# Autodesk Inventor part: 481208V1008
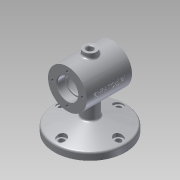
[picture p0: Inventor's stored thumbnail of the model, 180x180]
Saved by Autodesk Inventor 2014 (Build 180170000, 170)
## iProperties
Created: 2018-12
Part Number: 481208V1008
Material: 알루미늄 6061
Document SubType Name: Modeling
Designer: 601-05
Density: 2.71 g/cm^3
Appearance: 알루미늄 - 평지
Author: 601-05
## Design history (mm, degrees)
sketch "스케치1"
  geometry: C1 r 55 at (0, 0); 1 further point
  constraints: 1 centre point, 1 coincident
  dimensions: "d0" = 110 diameter of C1
extrude "돌출1" new body sketch "스케치1" distance "d1" = 11; taper "d2" = 0 deg
sketch "스케치2"
  geometry: L1 (0, 0)-(0, 75); L2 (-35, 75)-(35, 75); L3 (-35, 75)-(-35, 105); L4 (-35, 105)-(35, 105); L5 (35, 105)-(35, 75)
  constraints: 10 end point, 3 perpendicular, 1 midpoint, 1 parallel, 1 vertical
  dimensions: "d3" = 75 distance of L1.end L1.start; "d4" = 70 distance of L2.start L2.end; "d5" = 60 diameter of L4 L2
revolve "회전1" sketch "스케치2" stored, may be unused: angle "d6" = 90 deg
sketch "스케치3"
  geometry: L1 (-55, 0)-(-55, 11) reference; L2 (-55, 11)-(55, 11) reference; L3 (55, 11)-(55, 0) reference; L4 (55, 0)-(-55, 0) reference; L5 (-35, 45)-(-35, 105) reference; L6 (-35, 105)-(35, 105) reference; L7 (35, 105)-(35, 45) reference; L8 (35, 45)-(-35, 45) reference; L9 (0, 0)-(0, 75); L10 (-35, 75)-(-35, 91); L11 (-23, 90.7)-(-23, 89); L12 (-23, 89)-(-20, 89); L13 (-20, 89)-(-20, 97); L14 (-17, 100)-(17, 100); L15 (20, 97)-(20, 89); L16 (20, 89)-(23, 89); L17 (23, 89)-(23, 90.7); L18 (23.3, 91)-(35, 91); L19 (35, 91)-(35, 75); L20 (-23.3, 91)-(-35, 91); L21 (-35, 75)-(35, 75); A1 r 3 centre (-17, 97) between (-17, 100) and (-20, 97); A2 r 3 centre (17, 97) between (20, 97) and (17, 100); A3 r 0.3 centre (-23.3, 90.7) between (-23, 90.7) and (-23.3, 91); A4 r 0.3 centre (23.3, 90.7) between (23.3, 91) and (23, 90.7); 4 further points
  constraints: 26 end point, 10 point on line, 8 point on circle, 8 tangent, 6 parallel, 4 centre point, 3 perpendicular, 2 horizontal, 2 midpoint, 1 collinear, 1 equal radius
  dimensions: "d7" = 32 diameter of L20 L21; "d8" = 28 diameter of L12 L21; "d9" = 50 diameter of L14 L21; "d10" = 32 diameter of L18 L21; "d11" = 28 diameter of L16 L21; "d12" = 12 distance from line of point (-23, 91) L10; "d13" = 40 distance between parallel lines of L15 L13; "d14" = 12 distance of L18.end point (23, 91); "d15" = 3 distance between parallel lines of L13 L11; "d17" = 3 radius of A1; "d73" = 0.3 radius of A3; "d74" = 0.3 radius of A4
revolve "회전2" sketch "스케치3" stored, may be unused: angle "d16" = 90 deg
sketch "스케치4" dims "d19" = 46
  geometry: L1 (0, 0)-(0, 23); C1 r 30 at (0, 0) reference; 2 further points
  constraints: 2 coincident, 2 end point, 1 vertical, 1 vertical alignment, 2 other
hole "구멍1" sketch "스케치4" at (0, 23) diameter "d20" = 4.134; stored, may be unused: countersink angle "d24" = 90 deg, drill point angle "d26" = 118 deg; dims "d21" = 8, "d22" = 4, "d23" = 2, "d25" = 10
node "작업 평면1"
sketch "스케치5"
  geometry: L1 (0, -18.566)-(0, 13.615); L2 (35, 30)-(35, -30) reference; C1 r 10 at (0, 0); 1 further point
  constraints: 2 end point, 1 centre point, 1 coincident, 1 vertical
  dimensions: "d31" = 35 distance between parallel lines of L1 L2; "d32" = 20 diameter of C1
extrude "돌출2" join sketch "스케치5" stored distance "d33" = 10; taper "d34" = 0 deg
sketch "스케치6"
  geometry: C1 r 10 at (0, 0) reference; C2 r 5 at (0, 0)
  constraints: 1 centre point, 1 coincident
  dimensions: "d35" = 10 diameter of C2
extrude "돌출3" cut sketch "스케치6" distance "d36" = 28; taper "d37" = 0 deg
sketch "스케치7"
  geometry: L1 (55, 11)-(0, 25.737); L2 (-55, 0)-(-55, 11) reference; L3 (-55, 11)-(55, 11) reference; L4 (55, 11)-(55, 0) reference; L5 (55, 0)-(-55, 0) reference; L6 (-23.758, 98)-(-25, 100.067) reference; L7 (-25, 100.067)-(-35, 100.067) reference; L8 (-35, 100.067)-(-35, 105) reference; L9 (-35, 105)-(-10, 105) reference; L10 (-10, 105)-(-10, 112) reference; L11 (-10, 112)-(-5, 112) reference; L12 (-5, 112)-(-5, 100) reference; L13 (-5, 100)-(-17, 100) reference; L14 (-20, 97)-(-20, 89) reference; L15 (-20, 89)-(-23, 89) reference; L16 (-23, 89)-(-23, 90.7) reference; L17 (-23.3, 91)-(-35, 91) reference; L18 (-35, 91)-(-35, 95.933) reference; L19 (-35, 95.933)-(-25, 95.933) reference; L20 (-25, 95.933)-(-23.758, 98) reference; L21 (35, 91)-(23.3, 91) reference; L22 (23, 90.7)-(23, 89) reference; L23 (23, 89)-(20, 89) reference; L24 (20, 89)-(20, 97) reference; L25 (17, 100)-(5, 100) reference; L26 (5, 100)-(5, 112) reference; L27 (5, 112)-(10, 112) reference; L28 (10, 112)-(10, 105) reference; L29 (10, 105)-(35, 105) reference; L30 (35, 105)-(35, 100.067) reference; L31 (35, 100.067)-(25, 100.067) reference; L32 (25, 100.067)-(23.758, 98) reference; L33 (23.758, 98)-(25, 95.933) reference; L34 (25, 95.933)-(35, 95.933) reference; L35 (35, 95.933)-(35, 91) reference; L36 (23.3, 59)-(35, 59) reference; L37 (35, 59)-(35, 54.067) reference; L38 (35, 54.067)-(25, 54.067) reference; L39 (25, 54.067)-(23.758, 52) reference; L40 (23.758, 52)-(25, 49.933) reference; L41 (25, 49.933)-(35, 49.933) reference; L42 (35, 49.933)-(35, 45) reference; L43 (35, 45)-(-35, 45) reference; L44 (-35, 45)-(-35, 49.933) reference; L45 (-35, 49.933)-(-25, 49.933) reference; L46 (-25, 49.933)-(-23.758, 52) reference; L47 (-23.758, 52)-(-25, 54.067) reference; L48 (-25, 54.067)-(-35, 54.067) reference; L49 (-35, 54.067)-(-35, 59) reference; L50 (-35, 59)-(-23.3, 59) reference; L51 (-23, 59.3)-(-23, 61) reference; L52 (-23, 61)-(-20, 61) reference; L53 (-20, 61)-(-20, 53) reference; L54 (-17, 50)-(17, 50) reference; L55 (20, 53)-(20, 61) reference; L56 (20, 61)-(23, 61) reference; L57 (23, 61)-(23, 59.3) reference; L58 (20, 10)-(23, 10); L59 (55, 11)-(0, 11); L60 (0, 25.737)-(0, 11); A1 r 3 centre (-17, 97) between (-17, 100) and (-20, 97) reference; A2 r 0.3 centre (-23.3, 90.7) between (-23, 90.7) and (-23.3, 91) reference; A3 r 3 centre (17, 97) between (20, 97) and (17, 100) reference; A4 r 0.3 centre (-23.3, 59.3) between (-23.3, 59) and (-23, 59.3) reference; A5 r 3 centre (-17, 53) between (-20, 53) and (-17, 50) reference; A6 r 3 centre (17, 53) between (17, 50) and (20, 53) reference; A7 r 0.3 centre (23.3, 90.7) between (23.3, 91) and (23, 90.7) reference; A8 r 0.3 centre (23.3, 59.3) between (23, 59.3) and (23.3, 59) reference; 1 further point
  constraints: 8 end point, 5 point on line, 1 midpoint, 1 parallel, 1 perpendicular
  dimensions: "d38" = 75 deg angle of L4 L1
revolve "회전3" sketch "스케치7" stored, may be unused: angle "d39" = 90 deg
sketch "스케치8"
  geometry: C1 r 55 at (0, 0) reference; C2 r 12 at (0, 0)
  constraints: 1 centre point, 1 coincident
  dimensions: "d40" = 24 diameter of C2
extrude "돌출4" join sketch "스케치8" stored distance "d41" = 28; taper "d42" = 0 deg
sketch "스케치9" dims "d43" = 88
  geometry: L1 (0, 0)-(0, 44); L2 (0, 0)-(-44, 0); L3 (0, 0)-(0, -44); L4 (0, 0)-(44, 0); C1 r 55 at (0, 0) reference; C2 r 4.5 at (0, 44); C3 r 4.5 at (-44, 0); C4 r 4.5 at (0, -44); C5 r 4.5 at (44, 0); 3 further points
  constraints: 10 coincident, 8 end point, 4 centre point, 2 horizontal alignment, 2 vertical alignment, 1 vertical, 35 other
  dimensions: "d44" = 9 diameter of C2; "d47" = 360 deg dimension on L1.start L1.end (derived)
extrude "돌출5" cut sketch "스케치9" distance "d49" = 28; taper "d50" = 0 deg
node "작업 평면2"
sketch "스케치10"
  geometry: C1 r 4.5 at (0, 44) reference; C2 r 7 at (0, 44); C3 r 55 at (0, 0) reference; C4 r 7 at (-44, 0); C5 r 7 at (0, -44); C6 r 7 at (44, 0); 1 further point
  constraints: 4 centre point, 1 coincident, 9 other
  dimensions: "d52" = 14 diameter of C2; "d55" = 360 deg dimension on C3.centre C2.centre (derived)
extrude "돌출6" cut sketch "스케치10" distance "d57" = 28; taper "d58" = 0 deg
chamfer "모따기1" distance "d59" = 1; stored, may be unused: second distance "d60" = 2, angle "d61" = 45 deg
chamfer "모따기2" distance "d62" = 1; stored, may be unused: second distance "d63" = 2, angle "d64" = 45 deg
chamfer "모따기3" distance "d65" = 1; stored, may be unused: second distance "d66" = 2, angle "d67" = 45 deg
fillet "모깎기1" dims "d68" = 3
node "작업 평면3"
sketch "스케치11"
  geometry: L1 (-18.891, 0)-(20.217, 0); L2 (0, 24.26)-(0, -11.864); L3 (-35, -30)-(-35, 30) reference; L4 (-35, 30)-(35, 30) reference; 3 further points
  constraints: 4 end point, 2 point on line, 1 coincident, 1 horizontal, 1 perpendicular, 1 other
  dimensions: "d69" = 35 distance between parallel lines of L2 L3; "d70" = 30 distance between parallel lines of L1 L4
feature "엠보싱1" sketch "스케치11" dims "d71" = 0.5, "d72" = 0
node "솔리드1"
pattern_circular "원형 패턴1" dims angle "d28" = 360 deg
mirror "대칭1"
node "절단 모서리 투영1"
node "절단 모서리 투영2"
other parameters: "d30" = 112
